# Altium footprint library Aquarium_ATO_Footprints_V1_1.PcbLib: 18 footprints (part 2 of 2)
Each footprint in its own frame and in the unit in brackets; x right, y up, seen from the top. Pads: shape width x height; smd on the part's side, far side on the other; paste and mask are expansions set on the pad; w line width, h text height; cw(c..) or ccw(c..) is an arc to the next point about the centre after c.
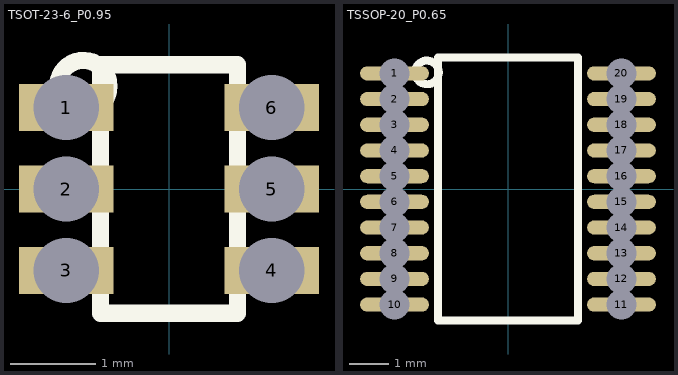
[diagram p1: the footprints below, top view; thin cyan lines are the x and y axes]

## TSOT-23-6_P0.95 [mm]
pads (6):
  rect 1.1x0.55 smd: 1(-1.2,0.95) 2(-1.2,0) 3(-1.2,-0.95) 4(1.2,-0.95) 5(1.2,0) 6(1.2,0.95)
Top Overlay:
  circle w0.2: c-1,1.2 r0.3
  lines w0.2: -0.8,-1.45 -0.8,1.45 0.8,1.45 0.8,-1.45 -0.8,-1.45

## TSSOP-20_P0.65 [mm]
pads (20):
  oval 1.74x0.36 smd: 1(-2.87,2.925) 2(-2.87,2.275) 3(-2.87,1.625) 4(-2.87,0.975) 5(-2.87,0.325) 6(-2.87,-0.325) 7(-2.87,-0.975) 8(-2.87,-1.625) 9(-2.87,-2.275) 10(-2.87,-2.925) 11(2.87,-2.925) 12(2.87,-2.275) 13(2.87,-1.625) 14(2.87,-0.975) 15(2.87,-0.325) 16(2.87,0.325) 17(2.87,0.975) 18(2.87,1.625) 19(2.87,2.275) 20(2.87,2.925)
Top Overlay:
  circle w0.2: c-2.05,2.95 r0.3
  lines w0.2: -1.77,-3.33 -1.77,3.33 1.77,3.33 1.77,-3.33 -1.77,-3.33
